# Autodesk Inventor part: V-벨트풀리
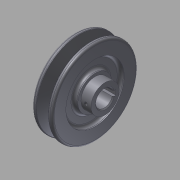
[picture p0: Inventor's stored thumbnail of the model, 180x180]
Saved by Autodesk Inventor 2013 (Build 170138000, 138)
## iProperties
Company: 한국ATC센터
Created: 2014-07
Part Number: V-벨트풀리
Document SubType Name: Modeling
Designer: KYOUNG IL JANG
Density: 7.87 g/cm^3
Material: 강철, 탄소
Mass: 593.765 g
Surface Area: 234.121 cm^2
Volume: 75.4466 cm^3
Author: KYOUNG IL JANG
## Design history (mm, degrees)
sketch "스케치1"
  geometry: L1 (-15, 0)-(15, 0); L2 (-15, 0)-(-15, 17); L3 (-15, 17)-(-11, 17); L4 (-11, 17)-(-11, 29); L5 (-11, 29)-(-15, 29); L6 (-15, 29)-(-15, 42.5); L7 (-15, 42.5)-(-10.976, 42.5); L8 (-10.976, 42.5)-(-7.154, 30); L9 (-7.154, 30)-(-2.846, 30); L10 (-2.846, 30)-(0.976, 42.5); L11 (0.976, 42.5)-(5, 42.5); L12 (5, 42.5)-(5, 29); L13 (5, 29)-(1, 29); L14 (1, 29)-(1, 17); L15 (1, 17)-(5, 17); L16 (5, 17)-(5, 14); L17 (5, 14)-(15, 14); L18 (15, 14)-(15, 0); L19 (-9.6, 38)-(-0.4, 38); 2 further points
  constraints: 38 end point, 11 parallel, 7 collinear, 3 equal length, 3 perpendicular, 2 point on line, 1 coincident, 1 horizontal, 1 midpoint
  dimensions: "d0" = 30 distance of L1.start L1.end; "d1" = 4.5 distance between parallel lines of L7 L19; "d2" = 8 distance between parallel lines of L9 L19; "d3" = 9.2 distance of L19.start L19.end; "d4" = 34 deg angle of L10 L8; "d5" = 20 distance between parallel lines of L12 L6; "d6" = 76 diameter of L19 L1; "d7" = 4 distance of L2.end L3.end; "d8" = 34 diameter of L3 L1; "d9" = 58 diameter of L5 L1; "d10" = 28 diameter of L17 L1
revolve "회전1" sketch "스케치1" stored, may be unused: angle "d11" = 90 deg
sketch "스케치2"
  geometry: L1 (-2.5, 8.124)-(-2.5, 10.8); L2 (-2.5, 10.8)-(2.5, 10.8); L3 (2.5, 10.8)-(2.5, 8.124); A1 r 8.5 centre (0, 0) between (-2.5, 8.124) and (2.5, 8.124); 1 further point
  constraints: 6 end point, 2 parallel, 2 point on circle, 1 centre point, 1 coincident, 1 horizontal, 1 vertical
  dimensions: "d12" = 17 diameter of A1; "d13" = 5 distance of L1.end L2.end; "d14" = 19.3 dimension on A1 L2 (computed from d12)
extrude "돌출1" cut sketch "스케치2" stored distance "d15" = 10; taper "d16" = 0 deg
chamfer "모따기1" distance "d17" = 1; stored, may be unused: second distance "d18" = 2, angle "d19" = 45 deg
node "작업 평면1"
sketch "스케치3"
  geometry: L1 (5, -14)-(5, 14) reference; 3 further points
  constraints: 1 horizontal alignment, 1 midpoint
  dimensions: "d20" = 5 distance from line of L1 point (0, 0)
hole "구멍1" sketch "스케치3" at (0, 0) diameter "d21" = 3.242; stored, may be unused: countersink angle "d25" = 90 deg, drill point angle "d27" = 118 deg; dims "d22" = 6, "d23" = 4, "d24" = 2, "d26" = 8
fillet "모깎기1" dims "d28" = 3, "d29" = 2, "d30" = 0.5, "d31" = 1
node "솔리드1"
